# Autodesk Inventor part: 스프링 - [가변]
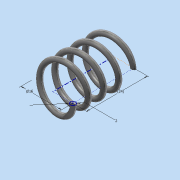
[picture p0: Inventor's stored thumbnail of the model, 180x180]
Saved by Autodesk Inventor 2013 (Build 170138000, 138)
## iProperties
Created: 2015-09
Part Number: 스프링 - [가변]
Material: 강철, 탄소
Document SubType Name: Modeling
Designer: WINDOWS7
Mass: 4.92033 g
Surface Area: 12.7475 cm^2
Volume: 0.625201 cm^3
Density: 7.87 g/cm^3
Author: WINDOWS7
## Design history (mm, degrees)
sketch "스케치1"
  geometry: L1 (0, 0)-(8, 0); L2 (8, 0)-(8, 42); L3 (8, 42)-(0, 42); L4 (0, 42)-(0, 0); C1 r 1 at (8, 0)
  constraints: 8 end point, 2 parallel, 1 centre point, 1 coincident, 1 horizontal, 1 perpendicular
  dimensions: "d0" = 2 diameter of C1; "d2" = 16 diameter of L2 L4; "d3" = 42 distance between parallel lines of L1 L3 (derived)
feature "코일1" pitch "d4" = 10; turns "d6" = 4; dims "d5" = 42 (= d3), "d7" = 0, angle "d8" = 90 deg, angle "d9" = 90 deg, "d10" = 0, "d11" = 0
node "작업 평면1"
node "작업 평면2"
sketch "스케치2"
  geometry: L1 (0, 0)-(2, 0) reference; 1 further point
  constraints: 1 horizontal alignment
  node "절단 모서리 투영1"
sketch "스케치3"
  geometry: L1 (2, 0)-(0, 0) reference; 1 further point
  constraints: 1 horizontal alignment
  node "절단 모서리 투영2"
extrude "돌출1" cut sketch "스케치2" distance "d12" = 10; taper "d13" = 0 deg
extrude "돌출2" cut sketch "스케치3" distance "d14" = 10; taper "d15" = 0 deg
node "솔리드1"
